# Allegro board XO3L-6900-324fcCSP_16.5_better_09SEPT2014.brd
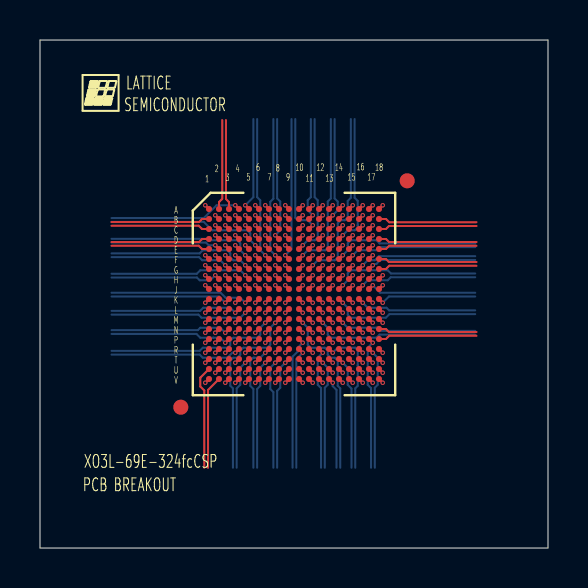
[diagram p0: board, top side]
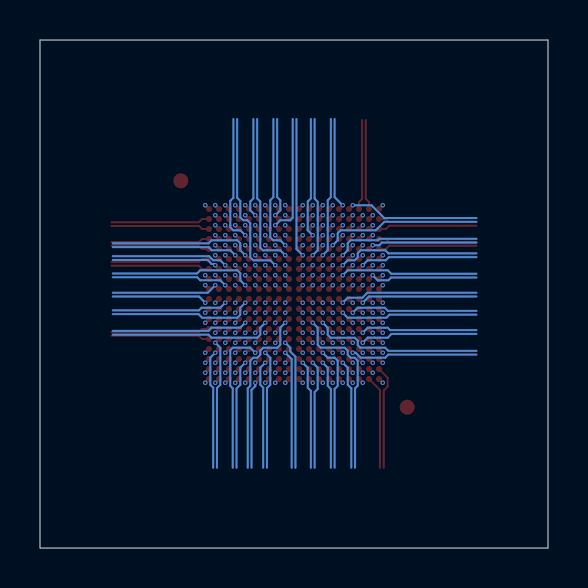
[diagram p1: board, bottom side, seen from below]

Outline 25.4 x 25.4 mm; copper layers: TOP, L2_GND, L3_SIGNAL1, L4_SIGNAL2, L5_GND, L6_SIG3, L5_PWR, BOTTOM. Coordinates in mm from the lower left corner of the outline.
Outline path: 0,25.4 25.4,25.4 25.4,0 0,0 0,25.4

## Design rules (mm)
net group CDPB4: nets PB4C PB4D
net group CDPB6: nets PB6C PB6D
net group CDPB7: nets PB7C PB7D
net group CDPB9: nets PB9C PB9D
net group CDPB13: nets PB13C PB13D
net group CDPB15: nets PB15C PB15D
net group CDPB16: nets PB16C PB16D
net group CDPB18: nets PB18C PB18D
net group CDPB21: nets PB21C PB21D
net group CDPB23: nets PB23C PB23D
net group CDPB26: nets PB26C PB26D
net group CDPB31: nets PB31C PB31D
net group CDPB35: nets PB35C PB35D
net group CDPB37: nets PB37C PB37D
net group CDPB38: nets PB38C PB38D
net group CDPL2: nets PL2C PL2D
net group CDPL3: nets PL3C PL3D
net group CDPL4: nets PL4C PL4D
net group CDPL5: nets PL5C PL5D
net group CDPL6: nets PL6C PL6D
net group CDPL7: nets PL7C PL7D
net group CDPL9: nets PL9C PL9D
net group CDPL10: nets PL10C PL10D
net group CDPL15: nets PL15C PL15D
net group CDPL16: nets PL16C PL16D
net group CDPL18: nets PL18C PL18D
net group CDPL19: nets PL19C PL19D
net group CDPL21: nets PL21C PL21D
net group CDPL23: nets PL23C PL23D
net group CDPL24: nets PL24C PL24D
net group CDPL25: nets PL25C PL25D
net group CDPR2: nets PR2C PR2D
net group CDPR3: nets PR3C PR3D
net group CDPR4: nets PR4C PR4D
net group CDPR6: nets PR6C PR6D
net group CDPR7: nets PR7C PR7D
net group CDPR8: nets PR8C PR8D
net group CDPR10: nets PR10C PR10D
net group CDPR11: nets PR11C PR11D
net group CDPR16: nets PR16C PR16D
net group CDPR17: nets PR17C PR17D
net group CDPR19: nets PR19C PR19D
net group CDPR21: nets PR21C PR21D
net group CDPR22: nets PR22C PR22D
net group CDPR23: nets PR23C PR23D
net group CDPR24: nets PR24C PR24D
net group CDPR25: nets PR25C PR25D
net group CDPT9: nets PT9C PT9D
net group CDPT10: nets PT10C PT10D
net group CDPT11: nets PT11C PT11D
net group CDPT14: nets PT14C PT14D
net group CDPT17: nets PT17C PT17D
net group CDPT18: nets PT18C PT18D
net group CDPT21: nets PT21C PT21D
net group CDPT22: nets PT22C PT22D
net group CDPT25: nets PT25C PT25D
net group CDPT26: nets PT26C PT26D
net group CDPT27: nets PT27C PT27D
net group CDPT33: nets PT33C PT33D
net group CDPT34: nets PT34C PT34D
net group CDPT35: nets PT35C PT35D
net group CDPT36: nets PT36C PT36D
net group DP1: nets PB16A PB16B
net group DP2: nets PB7A PB7B
net group DP3: nets PB13A PB13B
net group DP4: nets PB18A PB18B
net group PB4: nets PB4A PB4B
net group PB6: nets PB6A PB6B
net group PB9: nets PB9A PB9B
net group PB10: nets PB10A PB10B
net group PB12: nets PB12A PB12B
net group PB15: nets PB15A PB15B
net group PB21: nets PB21A PB21B
net group PB23: nets PB23A PB23B
net group PB26: nets PB26A PB26B
net group PB28: nets PB28A PB28B
net group PB29: nets PB29A PB29B
net group PB31: nets PB31A PB31B
net group PB32: nets PB32A PB32B
net group PB34: nets PB34A PB34B
net group PB35: nets PB35A PB35B
net group PB37: nets PB37A PB37B
net group PB38: nets PB38A PB38B
net group PL2: nets PL2A PL2B
net group PL3: nets PL3A PL3B
net group PL4: nets PL4A PL4B
net group PL5: nets PL5A PL5B
net group PL6: nets PL6A PL6B
net group PL8: nets PL8A PL8B
net group PL9: nets PL9A PL9B
net group PL10: nets PL10A PL10B
net group PL11: nets PL11A PL11B
net group PL12: nets PL12A PL12B
net group PL15: nets PL15A PL15B
net group PL17: nets PL17A PL17B
net group PL18: nets PL18A PL18B
net group PL19: nets PL19A PL19B
net group PL22: nets PL22A PL22B
net group PL23: nets PL23A PL23B
net group PL24: nets PL24A PL24B
net group PL25: nets PL25A PL25B
net group PR2: nets PR2A PR2B
net group PR3: nets PR3A PR3B
net group PR4: nets PR4A PR4B
net group PR5: nets PR5A PR5B
net group PR7: nets PR7A PR7B
net group PR8: nets PR8A PR8B
net group PR9: nets PR9A PR9B
net group PR11: nets PR11A PR11B
net group PR12: nets PR12A PR12B
net group PR15: nets PR15A PR15B
net group PR16: nets PR16A PR16B
net group PR17: nets PR17A PR17B
net group PR18: nets PR18A PR18B
net group PR21: nets PR21A PR21B
net group PR22: nets PR22A PR22B
net group PR23: nets PR23A PR23B
net group PR24: nets PR24A PR24B
net group PR25: nets PR25A PR25B
net group PT9: nets PT9A PT9B
net group PT10: nets PT10A PT10B
net group PT11: nets PT11A PT11B
net group PT12: nets PT12A PT12B
net group PT13: nets PT13A PT13B
net group PT14: nets PT14A PT14B
net group PT15: nets PT15A PT15B
net group PT16: nets PT16A PT16B
net group PT17: nets PT17A PT17B
net group PT18: nets PT18A PT18B
net group PT21: nets PT21A PT21B
net group PT22: nets PT22A PT22B
net group PT25: nets PT25A PT25B
net group PT26: nets PT26A PT26B
net group PT27: nets PT27A PT27B
net group PT28: nets PT28A PT28B
net group PT32: nets PT32A PT32B
net group PT33: nets PT33A PT33B
net group PT34: nets PT34A PT34B
net group PT35: nets PT35A PT35B
net group PT36: nets PT36A PT36B

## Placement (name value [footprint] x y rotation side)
BGA  -  [BGA324N50P18X18_1000X1000X10-1]  12.7 12.7 270 top
NOREF  -  []  1.85 21.54 0 top

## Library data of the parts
BGA = BGA324N50P18X18_1000X1000X10-1

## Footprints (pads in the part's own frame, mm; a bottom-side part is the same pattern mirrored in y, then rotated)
BGA324N50P18X18_1000X1000X10-1
  round 0.75 smd: (-5.66,5.66) (5.66,-5.66)
  round 0.305 smd: A1(-4.25,-4.25) A2(-4.25,-3.75) A3(-4.25,-3.25) A4(-4.25,-2.75) A5(-4.25,-2.25) A6(-4.25,-1.75) A7(-4.25,-1.25) A8(-4.25,-0.75) A9(-4.25,-0.25) A10(-4.25,0.25) A11(-4.25,0.75) A12(-4.25,1.25) A13(-4.25,1.75) A14(-4.25,2.25) A15(-4.25,2.75) A16(-4.25,3.25) A17(-4.25,3.75) A18(-4.25,4.25) B1(-3.75,-4.25) B2(-3.75,-3.75) B3(-3.75,-3.25) B4(-3.75,-2.75) B5(-3.75,-2.25) B6(-3.75,-1.75) B7(-3.75,-1.25) B8(-3.75,-0.75) B9(-3.75,-0.25) B10(-3.75,0.25) B11(-3.75,0.75) B12(-3.75,1.25) B13(-3.75,1.75) B14(-3.75,2.25) B15(-3.75,2.75) B16(-3.75,3.25) B17(-3.75,3.75) B18(-3.75,4.25) C1(-3.25,-4.25) C2(-3.25,-3.75) C3(-3.25,-3.25) C4(-3.25,-2.75) C5(-3.25,-2.25) C6(-3.25,-1.75) C7(-3.25,-1.25) C8(-3.25,-0.75) C9(-3.25,-0.25) C10(-3.25,0.25) C11(-3.25,0.75) C12(-3.25,1.25) C13(-3.25,1.75) C14(-3.25,2.25) C15(-3.25,2.75) C16(-3.25,3.25) C17(-3.25,3.75) C18(-3.25,4.25) D1(-2.75,-4.25) D2(-2.75,-3.75) D3(-2.75,-3.25) D4(-2.75,-2.75) D5(-2.75,-2.25) D6(-2.75,-1.75) D7(-2.75,-1.25) D8(-2.75,-0.75) D9(-2.75,-0.25) D10(-2.75,0.25) D11(-2.75,0.75) D12(-2.75,1.25) D13(-2.75,1.75) D14(-2.75,2.25) D15(-2.75,2.75) D16(-2.75,3.25) D17(-2.75,3.75) D18(-2.75,4.25) E1(-2.25,-4.25) E2(-2.25,-3.75) E3(-2.25,-3.25) E4(-2.25,-2.75) E5(-2.25,-2.25) E6(-2.25,-1.75) E7(-2.25,-1.25) E8(-2.25,-0.75) E9(-2.25,-0.25) E10(-2.25,0.25) E11(-2.25,0.75) E12(-2.25,1.25) E13(-2.25,1.75) E14(-2.25,2.25) E15(-2.25,2.75) E16(-2.25,3.25) E17(-2.25,3.75) E18(-2.25,4.25) F1(-1.75,-4.25) F2(-1.75,-3.75) F3(-1.75,-3.25) F4(-1.75,-2.75) F5(-1.75,-2.25) F6(-1.75,-1.75) F7(-1.75,-1.25) F8(-1.75,-0.75) F9(-1.75,-0.25) F10(-1.75,0.25) F11(-1.75,0.75) F12(-1.75,1.25) F13(-1.75,1.75) F14(-1.75,2.25) F15(-1.75,2.75) F16(-1.75,3.25) F17(-1.75,3.75) F18(-1.75,4.25) G1(-1.25,-4.25) G2(-1.25,-3.75) G3(-1.25,-3.25) G4(-1.25,-2.75) G5(-1.25,-2.25) G6(-1.25,-1.75) G7(-1.25,-1.25) G8(-1.25,-0.75) G9(-1.25,-0.25) G10(-1.25,0.25) G11(-1.25,0.75) G12(-1.25,1.25) G13(-1.25,1.75) G14(-1.25,2.25) G15(-1.25,2.75) G16(-1.25,3.25) G17(-1.25,3.75) G18(-1.25,4.25) H1(-0.75,-4.25) H2(-0.75,-3.75) H3(-0.75,-3.25) H4(-0.75,-2.75) H5(-0.75,-2.25) H6(-0.75,-1.75) H7(-0.75,-1.25) H8(-0.75,-0.75) H9(-0.75,-0.25) H10(-0.75,0.25) H11(-0.75,0.75) H12(-0.75,1.25) H13(-0.75,1.75) H14(-0.75,2.25) H15(-0.75,2.75) H16(-0.75,3.25) H17(-0.75,3.75) H18(-0.75,4.25) J1(-0.25,-4.25) J2(-0.25,-3.75) J3(-0.25,-3.25) J4(-0.25,-2.75) J5(-0.25,-2.25) J6(-0.25,-1.75) J7(-0.25,-1.25) J8(-0.25,-0.75) J9(-0.25,-0.25) J10(-0.25,0.25) J11(-0.25,0.75) J12(-0.25,1.25) J13(-0.25,1.75) J14(-0.25,2.25) J15(-0.25,2.75) J16(-0.25,3.25) J17(-0.25,3.75) J18(-0.25,4.25) K1(0.25,-4.25) K2(0.25,-3.75) K3(0.25,-3.25) K4(0.25,-2.75) K5(0.25,-2.25) K6(0.25,-1.75) K7(0.25,-1.25) K8(0.25,-0.75) K9(0.25,-0.25) K10(0.25,0.25) K11(0.25,0.75) K12(0.25,1.25) K13(0.25,1.75) K14(0.25,2.25) K15(0.25,2.75) K16(0.25,3.25) K17(0.25,3.75) K18(0.25,4.25) L1(0.75,-4.25) L2(0.75,-3.75) L3(0.75,-3.25) L4(0.75,-2.75) L5(0.75,-2.25) L6(0.75,-1.75) L7(0.75,-1.25) L8(0.75,-0.75) L9(0.75,-0.25) L10(0.75,0.25) L11(0.75,0.75) L12(0.75,1.25) L13(0.75,1.75) L14(0.75,2.25) L15(0.75,2.75) L16(0.75,3.25) L17(0.75,3.75) L18(0.75,4.25) M1(1.25,-4.25) M2(1.25,-3.75) M3(1.25,-3.25) M4(1.25,-2.75) M5(1.25,-2.25) M6(1.25,-1.75) M7(1.25,-1.25) M8(1.25,-0.75) M9(1.25,-0.25) M10(1.25,0.25) M11(1.25,0.75) M12(1.25,1.25) M13(1.25,1.75) M14(1.25,2.25) M15(1.25,2.75) M16(1.25,3.25) M17(1.25,3.75) M18(1.25,4.25) N1(1.75,-4.25) N2(1.75,-3.75) N3(1.75,-3.25) N4(1.75,-2.75) N5(1.75,-2.25) N6(1.75,-1.75) N7(1.75,-1.25) N8(1.75,-0.75) N9(1.75,-0.25) N10(1.75,0.25) N11(1.75,0.75) N12(1.75,1.25) N13(1.75,1.75) N14(1.75,2.25) N15(1.75,2.75) N16(1.75,3.25) N17(1.75,3.75) N18(1.75,4.25) P1(2.25,-4.25) P2(2.25,-3.75) P3(2.25,-3.25) P4(2.25,-2.75) P5(2.25,-2.25) P6(2.25,-1.75) P7(2.25,-1.25) P8(2.25,-0.75) P9(2.25,-0.25) P10(2.25,0.25) P11(2.25,0.75) P12(2.25,1.25) P13(2.25,1.75) P14(2.25,2.25) P15(2.25,2.75) P16(2.25,3.25) P17(2.25,3.75) P18(2.25,4.25) R1(2.75,-4.25) R2(2.75,-3.75) R3(2.75,-3.25) R4(2.75,-2.75) R5(2.75,-2.25) R6(2.75,-1.75) R7(2.75,-1.25) R8(2.75,-0.75) R9(2.75,-0.25) R10(2.75,0.25) R11(2.75,0.75) R12(2.75,1.25) R13(2.75,1.75) R14(2.75,2.25) R15(2.75,2.75) R16(2.75,3.25) R17(2.75,3.75) R18(2.75,4.25) T1(3.25,-4.25) T2(3.25,-3.75) T3(3.25,-3.25) T4(3.25,-2.75) T5(3.25,-2.25) T6(3.25,-1.75) T7(3.25,-1.25) T8(3.25,-0.75) T9(3.25,-0.25) T10(3.25,0.25) T11(3.25,0.75) T12(3.25,1.25) T13(3.25,1.75) T14(3.25,2.25) T15(3.25,2.75) T16(3.25,3.25) T17(3.25,3.75) T18(3.25,4.25) U1(3.75,-4.25) U2(3.75,-3.75) U3(3.75,-3.25) U4(3.75,-2.75) U5(3.75,-2.25) U6(3.75,-1.75) U7(3.75,-1.25) U8(3.75,-0.75) U9(3.75,-0.25) U10(3.75,0.25) U11(3.75,0.75) U12(3.75,1.25) U13(3.75,1.75) U14(3.75,2.25) U15(3.75,2.75) U16(3.75,3.25) U17(3.75,3.75) U18(3.75,4.25) V1(4.25,-4.25) V2(4.25,-3.75) V3(4.25,-3.25) V4(4.25,-2.75) V5(4.25,-2.25) V6(4.25,-1.75) V7(4.25,-1.25) V8(4.25,-0.75) V9(4.25,-0.25) V10(4.25,0.25) V11(4.25,0.75) V12(4.25,1.25) V13(4.25,1.75) V14(4.25,2.25) V15(4.25,2.75) V16(4.25,3.25) V17(4.25,3.75) V18(4.25,4.25)

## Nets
GND: BGA.A1 BGA.A18 BGA.F6 BGA.F13 BGA.J8 BGA.J9 BGA.J10 BGA.J11 BGA.K8 BGA.K9 BGA.K10 BGA.K11 BGA.N6 BGA.N13 BGA.V1 BGA.V18
VCC: BGA.H7 BGA.H12 BGA.J7 BGA.J12 BGA.K7 BGA.K12 BGA.L7 BGA.L12
VCCIO0: BGA.H8 BGA.H9 BGA.H10 BGA.H11
VCCIO1: BGA.H6 BGA.J6 BGA.K6 BGA.L6
VCCIO2: BGA.L8 BGA.L9 BGA.L10 BGA.L11
VCCIO3: BGA.L13 BGA.M13
VCCIO4: BGA.J13 BGA.K13
VCCIO5: BGA.G13 BGA.H13
PB4A: BGA.R15
PB4B: BGA.M11
PB4C: BGA.N11
PB4D: BGA.T15
PB6A: BGA.V17
PB6B: BGA.R14
PB6C: BGA.V16
PB6D: BGA.U16
PB7A: BGA.V14
PB7B: BGA.U14
PB7C: BGA.V15
PB7D: BGA.U15
PB9A: BGA.N10
PB9B: BGA.T13
PB9C: BGA.T14
PB9D: BGA.R13
PB10A: BGA.V13
PB10B: BGA.M10
PB12A: BGA.P13
PB12B: BGA.P12
PB13A: BGA.U13
PB13B: BGA.U12
PB13C: BGA.R12
PB13D: BGA.T12
PB15A: BGA.P11
PB15B: BGA.T11
PB15C: BGA.N9
PB15D: BGA.V12
PB16A: BGA.R11
PB16B: BGA.V11
PB16C: BGA.U11
PB16D: BGA.M9
PB18A: BGA.P10
PB18B: BGA.R10
PB18C: BGA.U10
PB18D: BGA.T10
PB21A: BGA.V10
PB21B: BGA.P9
PB21C: BGA.U9
PB21D: BGA.V9
PB23A: BGA.T9
PB23B: BGA.T8
PB23C: BGA.R9
PB23D: BGA.V8
PB26A: BGA.U8
PB26B: BGA.V7
PB26C: BGA.R8
PB26D: BGA.P8
PB28A: BGA.R7
PB28B: BGA.T7
PB29A: BGA.N8
PB29B: BGA.U7
PB31A: BGA.U6
PB31B: BGA.V6
PB31C: BGA.R6
PB31D: BGA.P6
PB32A: BGA.P7
PB32B: BGA.T6
PB34A: BGA.T5
PB34B: BGA.M8
PB35A: BGA.U5
PB35B: BGA.U4
PB35C: BGA.V5
PB35D: BGA.N7
PB37A: BGA.V4
PB37B: BGA.R5
PB37C: BGA.U3
PB37D: BGA.V3
PB38A: BGA.U2
PB38B: BGA.T4
PB38C: BGA.V2
PB38D: BGA.U1
PL2A: BGA.D16
PL2B: BGA.E15
PL2C: BGA.C17
PL2D: BGA.D17
PL3A: BGA.B18
PL3B: BGA.C18
PL3C: BGA.G12
PL3D: BGA.E17
PL4A: BGA.D18
PL4B: BGA.E18
PL4C: BGA.F15
PL4D: BGA.F14
PL5A: BGA.E16
PL5B: BGA.F16
PL5C: BGA.F17
PL5D: BGA.G14
PL6A: BGA.F18
PL6B: BGA.G18
PL6C: BGA.G15
PL6D: BGA.H14
PL7C: BGA.H17
PL7D: BGA.H15
PL8A: BGA.G16
PL8B: BGA.G17
PL9A: BGA.H16
PL9B: BGA.F12
PL9C: BGA.H18
PL9D: BGA.J15
PL10A: BGA.J14
PL10B: BGA.J16
PL10C: BGA.E14
PL10D: BGA.J18
PL11A: BGA.J17
PL11B: BGA.K18
PL12A: BGA.K17
PL12B: BGA.K15
PL15A: BGA.K16
PL15B: BGA.K14
PL15C: BGA.L17
PL15D: BGA.L14
PL16C: BGA.N12
PL16D: BGA.L15
PL17A: BGA.L18
PL17B: BGA.L16
PL18A: BGA.M16
PL18B: BGA.M18
PL18C: BGA.N14
PL18D: BGA.M17
PL19A: BGA.M15
PL19B: BGA.N17
PL19C: BGA.N16
PL19D: BGA.N15
PL21C: BGA.M14
PL21D: BGA.M12
PL22A: BGA.N18
PL22B: BGA.P18
PL23A: BGA.P15
PL23B: BGA.P16
PL23C: BGA.P17
PL23D: BGA.R17
PL24A: BGA.R16
PL24B: BGA.R18
PL24C: BGA.T17
PL24D: BGA.P14
PL25A: BGA.T18
PL25B: BGA.U17
PL25C: BGA.U18
PL25D: BGA.T16
PR2A: BGA.B1
PR2B: BGA.C1
PR2C: BGA.C3
PR2D: BGA.C2
PR3A: BGA.D1
PR3B: BGA.E1
PR3C: BGA.G7
PR3D: BGA.D3
PR4A: BGA.D2
PR4B: BGA.E4
PR4C: BGA.E3
PR4D: BGA.F3
PR5A: BGA.E2
PR5B: BGA.F5
PR6C: BGA.F4
PR6D: BGA.F2
PR7A: BGA.G6
PR7B: BGA.F1
PR7C: BGA.G5
PR7D: BGA.G3
PR8A: BGA.G4
PR8B: BGA.G2
PR8C: BGA.G1
PR8D: BGA.H4
PR9A: BGA.H5
PR9B: BGA.H2
PR10C: BGA.H3
PR10D: BGA.H1
PR11A: BGA.E5
PR11B: BGA.J5
PR11C: BGA.J4
PR11D: BGA.J1
PR12A: BGA.J3
PR12B: BGA.J2
PR15A: BGA.K1
PR15B: BGA.K2
PR16A: BGA.K3
PR16B: BGA.K5
PR16C: BGA.K4
PR16D: BGA.L3
PR17A: BGA.L1
PR17B: BGA.L2
PR17C: BGA.L5
PR17D: BGA.L4
PR18A: BGA.M1
PR18B: BGA.M6
PR19C: BGA.M3
PR19D: BGA.M4
PR21A: BGA.M2
PR21B: BGA.N1
PR21C: BGA.N2
PR21D: BGA.N4
PR22A: BGA.M5
PR22B: BGA.N5
PR22C: BGA.N3
PR22D: BGA.P3
PR23A: BGA.P2
PR23B: BGA.P1
PR23C: BGA.R1
PR23D: BGA.P4
PR24A: BGA.R2
PR24B: BGA.R3
PR24C: BGA.R4
PR24D: BGA.M7
PR25A: BGA.T1
PR25B: BGA.T2
PR25C: BGA.P5
PR25D: BGA.T3
PT9A: BGA.B16
PT9B: BGA.B17
PT9C: BGA.A17
PT9D: BGA.B15
PT10A: BGA.C16
PT10B: BGA.A15
PT10C: BGA.C14
PT10D: BGA.A16
PT11A: BGA.F11
PT11B: BGA.C15
PT11C: BGA.E13
PT11D: BGA.B14
PT12A: BGA.D13
PT12B: BGA.A14
PT12C: BGA.D15
PT13A: BGA.G11
PT13B: BGA.D14
PT14A: BGA.A13
PT14B: BGA.D12
PT14C: BGA.B13
PT14D: BGA.F10
PT15A: BGA.C13
PT15B: BGA.C12
PT16A: BGA.E12
PT16B: BGA.A12
PT16C: BGA.E11
PT17A: BGA.F9
PT17B: BGA.C11
PT17C: BGA.G10
PT17D: BGA.B12
PT18A: BGA.E10
PT18B: BGA.B11
PT18C: BGA.D11
PT18D: BGA.G9
PT21A: BGA.B10
PT21B: BGA.C10
PT21C: BGA.A11
PT21D: BGA.D10
PT22A: BGA.A10
PT22B: BGA.D9
PT22C: BGA.A9
PT22D: BGA.B9
PT25A: BGA.C9
PT25B: BGA.E9
PT25C: BGA.B8
PT25D: BGA.A8
PT26A: BGA.D8
PT26B: BGA.F8
PT26C: BGA.C8
PT26D: BGA.E8
PT27A: BGA.C7
PT27B: BGA.B3
PT27C: BGA.A7
PT27D: BGA.B7
PT28A: BGA.A6
PT28B: BGA.E7
PT32A: BGA.D7
PT32B: BGA.D6
PT33A: BGA.G8
PT33B: BGA.C6
PT33C: BGA.B5
PT33D: BGA.B6
PT34A: BGA.A4
PT34B: BGA.E6
PT34C: BGA.F7
PT34D: BGA.A5
PT35A: BGA.D4
PT35B: BGA.C5
PT35C: BGA.D5
PT35D: BGA.B2
PT36A: BGA.A3
PT36B: BGA.A2
PT36C: BGA.C4
PT36D: BGA.B4

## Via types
v1: diameter 0.224, hole 0.127, TOP to BOTTOM, 308 vias

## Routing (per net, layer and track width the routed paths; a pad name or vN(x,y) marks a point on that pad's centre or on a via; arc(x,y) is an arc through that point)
GND: length 4.2
  TOP w0.102: BGA.J8 v1(11.76,13.14) ; BGA.V18 v1(17.14,8.26) ; BGA.A18 v1(17.14,17.14) ; BGA.K10 v1(13.14,12.26) ; BGA.K9 v1(12.26,12.26) ; BGA.K11 v1(13.64,12.26) ; BGA.V1 v1(8.26,8.26) ; BGA.J11 v1(13.64,13.14) ; BGA.A1 v1(8.26,17.14) ; BGA.J10 v1(13.14,13.14) ; BGA.J9 v1(12.26,13.14) ; BGA.N6 v1(10.76,10.76) ; BGA.F6 v1(10.76,14.64) ; BGA.F13 v1(14.64,14.64) ; BGA.N13 v1(14.64,10.76) ; BGA.K8 v1(11.76,12.26)
VCC: length 2.1
  TOP w0.102: BGA.H12 v1(14.14,13.64) ; BGA.K12 v1(14.14,12.26) ; BGA.H7 v1(11.26,13.64) ; BGA.J7 v1(11.26,13.14) ; BGA.L12 v1(14.14,11.76) ; BGA.K7 v1(11.26,12.26) ; BGA.J12 v1(14.14,13.14) ; BGA.L7 v1(11.26,11.76)
VCCIO0: length 1.1
  TOP w0.102: BGA.H10 v1(13.14,13.64) ; BGA.H9 v1(12.26,13.64) ; BGA.H8 v1(11.76,13.64) ; BGA.H11 v1(13.64,13.64)
VCCIO1: length 1.1
  TOP w0.102: BGA.H6 v1(10.76,13.64) ; BGA.L6 v1(10.76,11.76) ; BGA.J6 v1(10.76,13.14) ; BGA.K6 v1(10.76,12.26)
VCCIO2: length 1.1
  TOP w0.102: BGA.L10 v1(13.14,11.76) ; BGA.L8 v1(11.76,11.76) ; BGA.L11 v1(13.64,11.76) ; BGA.L9 v1(12.26,11.76)
VCCIO3: length 0.5
  TOP w0.102: BGA.L13 v1(14.64,11.76) ; BGA.M13 v1(14.64,11.26)
VCCIO4: length 0.5
  TOP w0.102: BGA.J13 v1(14.64,13.14) ; BGA.K13 v1(14.64,12.26)
VCCIO5: length 0.5
  TOP w0.102: BGA.G13 v1(14.64,14.14) ; BGA.H13 v1(14.64,13.64)
PB4A: length 6.2
  TOP w0.102: BGA.R15 v1(15.64,9.76)
  L6_SIG3 w0.102: v1(15.64,9.76) 15.39,9.51 15.39,7.9 15.22,7.73 15.22,4.01
PB4B: length 8.5
  TOP w0.102: BGA.M11 v1(13.64,11.26)
  L6_SIG3 w0.102: 15.03,4.01 15.03,7.76 14.89,7.91 14.89,8.37 14.74,8.51 14.03,8.51 13.89,8.66 13.89,11.01 v1(13.64,11.26)
PB4C: length 10.1
  TOP w0.102: BGA.N11 v1(13.64,10.76)
  L4_SIGNAL2 w0.102: 21.82,8.87 17.44,8.87 17.29,9.01 16.03,9.01 15.89,9.16 15.89,9.87 15.74,10.01 15.57,10.01 15.53,10.01 15.39,10.16 15.39,10.37 15.24,10.51 14.53,10.51 14.39,10.66 14.39,10.86 14.24,11.01 13.89,11.01 v1(13.64,10.76)
PB4D: length 7
  TOP w0.102: BGA.T15 v1(15.64,9.26)
  L4_SIGNAL2 w0.102: v1(15.64,9.26) 15.64,9.12 15.89,8.87 15.89,8.66 16.03,8.51 17.24,8.51 17.41,8.68 21.82,8.68
PB6A: length 4.7
  TOP w0.102: BGA.V17 v1(16.64,8.26)
  L4_SIGNAL2 w0.102: 16.14,4.08 16.14,7.58 16.64,8.08 v1(16.64,8.26)
PB6B: length 6.3
  TOP w0.102: BGA.R14 v1(15.14,9.76)
  L4_SIGNAL2 w0.102: v1(15.14,9.76) 15.39,9.51 15.39,8.16 15.95,7.6 15.95,4.08
PB6C: length 4.5
  TOP w0.102: BGA.V16 v1(16.14,8.26)
  L6_SIG3 w0.102: 16.2,4.01 16.2,7.58 16.14,7.64 v1(16.14,8.26)
PB6D: length 5.1
  TOP w0.102: BGA.U16 v1(16.14,8.76)
  L6_SIG3 w0.102: v1(16.14,8.76) 16.39,8.51 16.39,8.26 16.39,8.26 16.39,4.01
PB7A: length 4.6
  TOP w0.102: BGA.V14 v1(15.14,8.26)
  L3_SIGNAL1 w0.102: 14.98,4.01 14.98,7.48 15.2,7.7 15.2,8.2 v1(15.14,8.26)
PB7B: length 5.2
  TOP w0.102: BGA.U14 v1(15.14,8.76)
  L3_SIGNAL1 w0.102: v1(15.14,8.76) 15.39,8.51 15.39,7.62 15.17,7.4 15.17,4.01
PB7C: length 4.6
  TOP w0.102: BGA.V15 v1(15.64,8.26)
  L3_SIGNAL1 w0.102: 15.48,4.01 15.48,7.25 15.57,7.34 15.57,7.35 15.7,7.48 15.7,8.2 v1(15.64,8.26)
PB7D: length 5.2
  TOP w0.102: BGA.U15 v1(15.64,8.76)
  L3_SIGNAL1 w0.102: v1(15.64,8.76) 15.89,8.51 15.89,7.39 15.67,7.17 15.67,4.01
PB9A: length 8.3
  TOP w0.102: BGA.N10 v1(13.14,10.76)
  L4_SIGNAL2 w0.102: v1(13.14,10.76) 13.39,10.51 13.76,10.51 13.89,10.39 13.89,10.16 14.03,10.01 14.74,10.01 14.89,9.87 14.89,9.2 14.89,9.2 14.89,8.07 14.73,7.92 14.73,4.11
PB9B: length 5.6
  TOP w0.102: BGA.T13 v1(14.64,9.26)
  L4_SIGNAL2 w0.102: v1(14.64,9.26) 14.39,9.01 14.39,8.08 14.54,7.92 14.54,7.67 14.54,7.67 14.54,4.11
PB9C: length 5.7
  TOP w0.102: BGA.T14 v1(15.14,9.26)
  BOTTOM w0.102: 15.57,4.01 15.57,7.97 15.39,8.16 15.39,9.01 v1(15.14,9.26)
PB9D: length 7.6
  TOP w0.102: BGA.R13 v1(14.64,9.76)
  BOTTOM w0.102: v1(14.64,9.76) 14.89,10.01 15.76,10.01 15.89,9.89 15.89,9.14 15.89,9.14 15.89,8.11 15.76,7.98 15.76,4.01
PB10A: length 4.6
  TOP w0.102: BGA.V13 v1(14.64,8.26)
  BOTTOM w0.102: v1(14.64,8.26) 14.64,8.09 14.82,7.9 14.82,4.01
PB10B: length 8.8
  TOP w0.102: BGA.M10 v1(13.14,11.26)
  BOTTOM w0.102: 15.01,4.01 15.01,7.98 14.89,8.11 14.89,9.37 14.74,9.51 14.54,9.51 14.39,9.66 14.39,9.87 14.24,10.01 13.54,10.01 13.39,10.16 13.39,11.01 v1(13.14,11.26)
PB12A: length 7.6
  TOP w0.102: BGA.P13 v1(14.64,10.26)
  L6_SIG3 w0.102: v1(14.64,10.26) 14.89,10.01 17.01,10.01 17.19,10.19 21.76,10.19
PB12B: length 8
  TOP w0.102: BGA.P12 v1(14.14,10.26)
  L6_SIG3 w0.102: v1(14.14,10.26) 14.39,10.51 17.01,10.51 17.15,10.38 21.76,10.38
PB13A: length 5.2
  TOP w0.102: BGA.U13 v1(14.64,8.76)
  L3_SIGNAL1 w0.102: v1(14.64,8.76) 14.89,8.51 14.89,8.16 14.7,7.98 14.7,4.01
PB13B: length 5.2
  TOP w0.102: BGA.U12 v1(14.14,8.76)
  L3_SIGNAL1 w0.102: 14.51,4.01 14.51,8.04 14.39,8.16 14.39,8.51 v1(14.14,8.76)
PB13C: length 6.2
  TOP w0.102: BGA.R12 v1(14.14,9.76)
  BOTTOM w0.102: v1(14.14,9.76) 13.89,9.51 13.89,8.87 13.89,8.87 13.89,8.16 14.05,8 14.05,4.01
PB13D: length 5.7
  TOP w0.102: BGA.T12 v1(14.14,9.26)
  BOTTOM w0.102: 14.24,4.01 14.24,8.01 14.39,8.16 14.39,9.01 v1(14.14,9.26)
PB15A: length 6.6
  TOP w0.102: BGA.P11 v1(13.64,10.26)
  L4_SIGNAL2 w0.102: v1(13.64,10.26) 13.39,10.01 13.39,8.11 13.54,7.95 13.54,4.08
PB15B: length 5.6
  TOP w0.102: BGA.T11 v1(13.64,9.26)
  L4_SIGNAL2 w0.102: v1(13.64,9.26) 13.89,9.01 13.89,8.11 13.73,7.95 13.73,4.08
PB15C: length 8.4
  TOP w0.102: BGA.N9 v1(12.26,10.76)
  L3_SIGNAL1 w0.102: v1(12.26,10.76) 12.51,10.51 13.74,10.51 13.89,10.36 13.89,7.67 13.91,7.65 13.91,4.01
PB15D: length 4.5
  TOP w0.102: BGA.V12 v1(14.14,8.26)
  L3_SIGNAL1 w0.102: v1(14.14,8.26) 14.14,7.66 14.1,7.62 14.1,4.01
PB16A: length 6.2
  TOP w0.102: BGA.R11 v1(13.64,9.76)
  L3_SIGNAL1 w0.102: 13.29,4.01 13.29,8.06 13.39,8.16 13.39,9.51 v1(13.64,9.76)
PB16B: length 4.6
  TOP w0.102: BGA.V11 v1(13.64,8.26)
  L3_SIGNAL1 w0.102: v1(13.64,8.26) 13.64,8.15 13.47,7.98 13.47,4.01
PB16C: length 5.2
  TOP w0.102: BGA.U11 v1(13.64,8.76)
  L6_SIG3 w0.102: v1(13.64,8.76) 13.39,8.51 13.39,8.16 13.2,7.98 13.2,4.01
PB16D: length 7.8
  TOP w0.102: BGA.M9 v1(12.26,11.26)
  L6_SIG3 w0.102: v1(12.26,11.26) 12.7,10.83 12.7,8.29 13.01,7.98 13.01,4.01
PB18A: length 6.7
  TOP w0.102: BGA.P10 v1(13.14,10.26)
  BOTTOM w0.102: 12.63,4.01 12.63,9.57 12.89,9.83 12.89,10.01 v1(13.14,10.26)
PB18B: length 6.1
  TOP w0.102: BGA.R10 v1(13.14,9.76)
  BOTTOM w0.102: 12.82,4.01 12.82,9.44 v1(13.14,9.76)
PB18C: length 5.5
  TOP w0.102: BGA.U10 v1(13.14,8.76)
  L4_SIGNAL2 w0.102: 12.78,4.08 12.78,8.82 12.88,8.92 12.98,8.92 v1(13.14,8.76)
PB18D: length 5.8
  TOP w0.102: BGA.T10 v1(13.14,9.26)
  L4_SIGNAL2 w0.102: 12.59,4.08 12.59,8.9 12.8,9.11 12.98,9.11 v1(13.14,9.26)
PB21A: length 4.6
  TOP w0.102: BGA.V10 v1(13.14,8.26)
  L3_SIGNAL1 w0.102: 12.95,4.01 12.95,8.08 v1(13.14,8.26)
PB21B: length 6.7
  TOP w0.102: BGA.P9 v1(12.26,10.26)
  L3_SIGNAL1 w0.102: 12.76,4.01 12.76,9.76 v1(12.26,10.26)
PB21C: length 5.1
  TOP w0.102: BGA.U9 v1(12.26,8.76)
  L3_SIGNAL1 w0.102: 12.51,4.01 12.51,8.51 v1(12.26,8.76)
PB21D: length 4.5
  TOP w0.102: BGA.V9 v1(12.26,8.26)
  L3_SIGNAL1 w0.102: v1(12.26,8.26) 12.26,7.98 12.32,7.92 12.32,4.01
PB23A: length 5.7
  TOP w0.102: BGA.T9 v1(12.26,9.26)
  BOTTOM w0.102: 11.86,4.01 11.86,7.86 12.01,8.01 12.01,9.01 v1(12.26,9.26)
PB23B: length 5.7
  TOP w0.102: BGA.T8 v1(11.76,9.26)
  BOTTOM w0.102: v1(11.76,9.26) 11.51,9.01 11.51,7.95 11.67,7.8 11.67,4.01
PB23C: length 6.1
  TOP w0.102: BGA.R9 v1(12.26,9.76)
  L3_SIGNAL1 w0.102: 12.01,4.01 12.01,9.51 v1(12.26,9.76)
PB23D: length 4.5
  TOP w0.102: BGA.V8 v1(11.76,8.26)
  L3_SIGNAL1 w0.102: v1(11.76,8.26) 11.76,8.01 11.83,7.95 11.83,4.01
PB26A: length 5.1
  TOP w0.102: BGA.U8 v1(11.76,8.76)
  L3_SIGNAL1 w0.102: v1(11.76,8.76) 11.51,8.51 11.51,4.01
PB26B: length 4.5
  TOP w0.102: BGA.V7 v1(11.26,8.26)
  L3_SIGNAL1 w0.102: 11.32,4.01 11.32,7.76 11.26,7.83 11.26,8.26 v1(11.26,8.26)
PB26C: length 6.2
  TOP w0.102: BGA.R8 v1(11.76,9.76)
  L4_SIGNAL2 w0.102: 11.67,4.08 11.67,7.92 11.51,8.08 11.51,9.53 11.68,9.7 11.76,9.7 11.76,9.7 v1(11.76,9.76)
PB26D: length 6.6
  TOP w0.102: BGA.P8 v1(11.76,10.26)
  L4_SIGNAL2 w0.102: 11.86,4.08 11.86,7.95 12.01,8.11 12.01,10.01 v1(11.76,10.26)
PB28A: length 6.6
  TOP w0.102: BGA.R7 v1(11.26,9.76)
  BOTTOM w0.102: v1(11.26,9.76) 11.01,9.51 11.01,9.51 10.7,9.51 10.7,9.51 10.66,9.51 10.51,9.37 10.51,8.11 10.67,7.95 10.67,4.01
PB28B: length 5.7
  TOP w0.102: BGA.T7 v1(11.26,9.26)
  BOTTOM w0.102: v1(11.26,9.26) 11.01,9.01 11.01,8.11 10.86,7.95 10.86,4.01
PB29A: length 7.2
  TOP w0.102: BGA.N8 v1(11.76,10.76)
  L6_SIG3 w0.102: 11.85,4.01 11.85,7.85 12.01,8.01 12.01,10.51 v1(11.76,10.76)
PB29B: length 5.2
  TOP w0.102: BGA.U7 v1(11.26,8.76)
  L6_SIG3 w0.102: 11.66,4.01 11.66,7.84 11.51,7.98 11.51,8.51 v1(11.26,8.76)
PB31A: length 5.1
  TOP w0.102: BGA.U6 v1(10.76,8.76)
  L3_SIGNAL1 w0.102: v1(10.76,8.76) 11.01,8.51 11.01,4.01
PB31B: length 4.5
  TOP w0.102: BGA.V6 v1(10.76,8.26)
  L3_SIGNAL1 w0.102: v1(10.76,8.26) 10.76,7.81 10.83,7.75 10.83,4.01
PB31C: length 6.2
  TOP w0.102: BGA.R6 v1(10.76,9.76)
  L6_SIG3 w0.102: 10.36,4.01 10.36,7.86 10.51,8.01 10.51,9.51 v1(10.76,9.76)
PB31D: length 7.1
  TOP w0.102: BGA.P6 v1(10.76,10.26)
  L6_SIG3 w0.102: 10.17,4.01 10.17,7.83 10.01,7.98 10.01,9.87 10.16,10.01 10.51,10.01 v1(10.76,10.26)
PB32A: length 6.6
  TOP w0.102: BGA.P7 v1(11.26,10.26)
  L4_SIGNAL2 w0.102: 10.89,4.08 10.89,7.89 11.01,8.01 11.01,10.01 v1(11.26,10.26)
PB32B: length 5.6
  TOP w0.102: BGA.T6 v1(10.76,9.26)
  L4_SIGNAL2 w0.102: v1(10.76,9.26) 10.51,9.01 10.51,8.04 10.7,7.86 10.7,4.08
PB34A: length 5.7
  TOP w0.102: BGA.T5 v1(10.26,9.26)
  BOTTOM w0.102: 9.83,4.01 9.83,7.98 10.01,8.16 10.01,9.01 v1(10.26,9.26)
PB34B: length 9.3
  TOP w0.102: BGA.M8 v1(11.76,11.26)
  BOTTOM w0.102: 9.65,4.01 9.65,7.98 9.51,8.11 9.51,9.37 9.66,9.51 9.86,9.51 10.01,9.66 10.01,9.87 10.16,10.01 11.37,10.01 11.51,10.16 11.51,11.01 v1(11.76,11.26)
PB35A: length 5.2
  TOP w0.102: BGA.U5 v1(10.26,8.76)
  L3_SIGNAL1 w0.102: v1(10.26,8.76) 10.51,8.51 10.51,7.95 10.31,7.75 10.31,4.01
PB35B: length 5.2
  TOP w0.102: BGA.U4 v1(9.76,8.76)
  L3_SIGNAL1 w0.102: 10.12,4.01 10.12,7.76 10.01,7.87 10.01,8.51 v1(9.76,8.76)
PB35C: length 4.5
  TOP w0.102: BGA.V5 v1(10.26,8.26)
  L4_SIGNAL2 w0.102: v1(10.26,8.26) 10.26,8.01 10.2,7.95 10.2,4.08
PB35D: length 7.8
  TOP w0.102: BGA.N7 v1(11.26,10.76)
  L4_SIGNAL2 w0.102: 10.01,4.08 10.01,9.36 10.16,9.51 10.33,9.51 10.33,9.51 10.37,9.51 10.51,9.66 10.51,9.7 10.51,9.7 10.51,10.37 10.66,10.51 11.01,10.51 v1(11.26,10.76)
PB37A: length 4.5
  TOP w0.102: BGA.V4 v1(9.76,8.26)
  L3_SIGNAL1 w0.102: 9.7,4.01 9.7,7.45 9.76,7.51 v1(9.76,8.26)
PB37B: length 6.5
  TOP w0.102: BGA.R5 v1(10.26,9.76)
  L3_SIGNAL1 w0.102: v1(10.26,9.76) 10.01,9.51 9.66,9.51 9.51,9.37 9.51,4.01
PB37C: length 5.2
  TOP w0.102: BGA.U3 v1(9.26,8.76)
  L3_SIGNAL1 w0.102: 8.83,4.01 8.83,7.24 9.01,7.43 9.01,8.51 v1(9.26,8.76)
PB37D: length 4.6
  TOP w0.102: BGA.V3 v1(9.26,8.26)
  L3_SIGNAL1 w0.102: 9.01,4.01 9.01,7.16 9.2,7.35 9.2,8.2 v1(9.26,8.26)
PB38A: length 5.2
  TOP w0.102: BGA.U2 v1(8.76,8.76)
  L6_SIG3 w0.102: v1(8.76,8.76) 9.01,8.51 9.01,8.01 9.17,7.86 9.17,4.01
PB38B: length 5.7
  TOP w0.102: BGA.T4 v1(9.76,9.26)
  L6_SIG3 w0.102: 9.36,4.01 9.36,7.89 9.51,8.04 9.51,9.01 v1(9.76,9.26)
PB38C: length 4.7
  TOP w0.102: BGA.V2 8.4,7.9 8.4,4.01
PB38D: length 5.2
  TOP w0.102: BGA.U1 8.01,8.51 8.01,8.08 8.21,7.88 8.21,4.01
PL2A: length 6.1
  TOP w0.102: BGA.D16 v1(16.14,15.64)
  L4_SIGNAL2 w0.102: v1(16.14,15.64) 16.28,15.64 16.53,15.89 16.89,15.89 17.04,15.73 21.82,15.73
PL2B: length 6.6
  TOP w0.102: BGA.E15 v1(15.64,15.14)
  L4_SIGNAL2 w0.102: 21.82,15.54 17.04,15.54 16.89,15.39 15.89,15.39 v1(15.64,15.14)
PL2C: length 5.5
  TOP w0.102: BGA.C17 v1(16.64,16.14)
  L3_SIGNAL1 w0.102: v1(16.64,16.14) 16.79,15.98 21.82,15.98
PL2D: length 5.5
  TOP w0.102: BGA.D17 v1(16.64,15.64)
  L3_SIGNAL1 w0.102: v1(16.64,15.64) 16.79,15.79 21.82,15.79
PL3A: length 4.9
  TOP w0.102: 21.82,16.29 17.46,16.29 17.3,16.45 BGA.B18
PL3B: length 4.9
  TOP w0.102: BGA.C18 17.3,15.95 17.45,16.1 21.82,16.1
PL3C: length 8.5
  TOP w0.102: BGA.G12 v1(14.14,14.14)
  L4_SIGNAL2 w0.102: 21.82,14.67 17.35,14.67 17.13,14.89 15.53,14.89 15.39,14.74 15.39,14.53 15.24,14.39 14.39,14.39 v1(14.14,14.14)
PL3D: length 5.6
  TOP w0.102: BGA.E17 v1(16.64,15.14)
  L4_SIGNAL2 w0.102: 21.82,14.86 17.43,14.86 17.15,15.14 v1(16.64,15.14)
PL4A: length 4.9
  TOP w0.102: BGA.D18 17.3,15.45 17.45,15.3 21.82,15.3
PL4B: length 4.9
  TOP w0.102: BGA.E18 17.3,14.95 17.46,15.11 21.82,15.11
PL4C: length 6.6
  TOP w0.102: BGA.F15 v1(15.64,14.64)
  BOTTOM w0.102: v1(15.64,14.64) 15.7,14.7 15.89,14.89 16.81,14.89 16.97,15.04 21.76,15.04
PL4D: length 7.5
  TOP w0.102: BGA.F14 v1(15.14,14.64)
  BOTTOM w0.102: v1(15.14,14.64) 15.39,14.89 15.39,15.12 15.39,15.24 15.53,15.39 16.83,15.39 16.98,15.23 21.76,15.23
PL5A: length 6.1
  TOP w0.102: BGA.E16 v1(16.14,15.14)
  L3_SIGNAL1 w0.102: v1(16.14,15.14) 16.39,15.39 16.95,15.39 17.11,15.23 21.82,15.23
PL5B: length 6.1
  TOP w0.102: BGA.F16 v1(16.14,14.64)
  L3_SIGNAL1 w0.102: 21.82,15.04 17.1,15.04 16.95,14.89 16.39,14.89 v1(16.14,14.64)
PL5C: length 5.5
  TOP w0.102: BGA.F17 v1(16.64,14.64)
  L3_SIGNAL1 w0.102: 21.82,14.57 17.07,14.57 17.01,14.64 v1(16.64,14.64)
PL5D: length 7.1
  TOP w0.102: BGA.G14 v1(15.14,14.14)
  L3_SIGNAL1 w0.102: 21.82,14.39 15.39,14.39 v1(15.14,14.14)
PL6A: length 4.9
  TOP w0.102: 21.82,14.3 17.45,14.3 17.3,14.45 BGA.F18
PL6B: length 4.9
  TOP w0.102: BGA.G18 17.3,13.95 17.46,14.11 21.82,14.11
PL6C: length 6.6
  TOP w0.102: BGA.G15 v1(15.64,14.14)
  L4_SIGNAL2 w0.102: v1(15.64,14.14) 15.89,14.39 16.83,14.39 17,14.21 21.82,14.21
PL6D: length 7.1
  TOP w0.102: BGA.H14 v1(15.14,13.64)
  L4_SIGNAL2 w0.102: v1(15.14,13.64) 15.39,13.89 16.82,13.89 16.96,14.03 21.82,14.03
PL7C: length 5.6
  TOP w0.102: BGA.H17 v1(16.64,13.64)
  L3_SIGNAL1 w0.102: v1(16.64,13.64) 16.75,13.64 17.01,13.89 21.82,13.89
PL7D: length 6.6
  TOP w0.102: BGA.H15 v1(15.64,13.64)
  L3_SIGNAL1 w0.102: v1(15.64,13.64) 15.89,13.89 16.74,13.89 16.93,14.08 21.82,14.08
PL8A: length 6.1
  TOP w0.102: BGA.G16 v1(16.14,14.14)
  BOTTOM w0.102: v1(16.14,14.14) 16.39,14.39 16.74,14.39 16.94,14.59 21.76,14.59
PL8B: length 5.5
  TOP w0.102: BGA.G17 v1(16.64,14.14)
  BOTTOM w0.102: 21.76,14.4 17.02,14.4 16.82,14.2 16.7,14.2 v1(16.64,14.14)
PL9A: length 6.1
  TOP w0.102: BGA.H16 v1(16.14,13.64)
  L4_SIGNAL2 w0.102: 21.82,13.19 17.43,13.19 17.24,13.39 16.39,13.39 v1(16.14,13.64)
PL9B: length 10.1
  TOP w0.102: BGA.F12 v1(14.14,14.64)
  L4_SIGNAL2 w0.102: v1(14.14,14.64) 13.89,14.39 13.89,13.01 14.07,12.82 17.23,12.82 17.41,13 21.82,13
PL9C: length 5.1
  TOP w0.102: BGA.H18 v1(17.14,13.64)
  L3_SIGNAL1 w0.102: v1(17.14,13.64) 17.84,13.64 18.15,13.32 21.82,13.32
PL9D: length 6.7
  TOP w0.102: BGA.J15 v1(15.64,13.14)
  L3_SIGNAL1 w0.102: v1(15.64,13.14) 15.89,13.39 17.82,13.39 18.07,13.14 21.82,13.14
PL10A: length 7.5
  TOP w0.102: BGA.J14 v1(15.14,13.14)
  BOTTOM w0.102: v1(15.14,13.14) 15.39,13.39 15.39,13.74 15.53,13.89 17.39,13.89 17.55,13.73 21.76,13.73
PL10B: length 6.1
  TOP w0.102: BGA.J16 v1(16.14,13.14)
  BOTTOM w0.102: v1(16.14,13.14) 16.39,13.39 16.39,13.39 17.39,13.39 17.54,13.54 21.76,13.54
PL10C: length 8.7
  TOP w0.102: BGA.E14 v1(15.14,15.14)
  L6_SIG3 w0.102: 21.76,14.08 18.01,14.08 17.32,13.39 15.54,13.39 15.39,13.54 15.39,14.89 v1(15.14,15.14)
PL10D: length 5.2
  TOP w0.102: BGA.J18 v1(17.14,13.14)
  L6_SIG3 w0.102: v1(17.14,13.14) 17.34,13.14 18.09,13.89 21.76,13.89
PL11A: length 5.5
  TOP w0.102: BGA.J17 v1(16.64,13.14)
  BOTTOM w0.102: 21.76,12.76 17.01,12.76 v1(16.64,13.14)
PL11B: length 5
  TOP w0.102: BGA.K18 v1(17.14,12.26)
  BOTTOM w0.102: 21.76,12.57 17.45,12.57 v1(17.14,12.26)
PL12A: length 5.7
  TOP w0.102: BGA.K17 v1(16.64,12.26)
  L3_SIGNAL1 w0.102: v1(16.64,12.26) 17,12.62 17.64,12.62 17.87,12.39 21.82,12.39
PL12B: length 6.8
  TOP w0.102: BGA.K15 v1(15.64,12.26)
  L3_SIGNAL1 w0.102: 21.82,12.58 17.95,12.58 17.7,12.82 16.2,12.82 v1(15.64,12.26)
PL15A: length 6
  TOP w0.102: BGA.K16 v1(16.14,12.26)
  BOTTOM w0.102: v1(16.14,12.26) 16.39,12.01 17.32,12.01 17.45,11.88 21.76,11.88
PL15B: length 7.5
  TOP w0.102: BGA.K14 v1(15.14,12.26)
  BOTTOM w0.102: v1(15.14,12.26) 15.39,12.01 15.39,11.66 15.54,11.51 17.29,11.51 17.47,11.69 21.76,11.69
PL15C: length 5.6
  TOP w0.102: BGA.L17 v1(16.64,11.76)
  L4_SIGNAL2 w0.102: 21.82,12.2 17.51,12.2 17.33,12.01 16.89,12.01 v1(16.64,11.76)
PL15D: length 7.6
  TOP w0.102: BGA.L14 v1(15.14,11.76)
  L4_SIGNAL2 w0.102: 21.82,12.39 17.51,12.39 17.32,12.58 15.6,12.58 15.39,12.36 15.39,12.01 v1(15.14,11.76)
PL16C: length 8
  TOP w0.102: BGA.N12 v1(14.14,10.76)
  L6_SIG3 w0.102: v1(14.14,10.76) 14.39,11.01 15.74,11.01 15.74,11.01 17.39,11.01 17.51,11.14 21.76,11.14
PL16D: length 6.6
  TOP w0.102: BGA.L15 v1(15.64,11.76)
  L6_SIG3 w0.102: 21.76,11.33 17.51,11.33 17.32,11.51 15.89,11.51 v1(15.64,11.76)
PL17A: length 5
  TOP w0.102: BGA.L18 v1(17.14,11.76)
  L3_SIGNAL1 w0.102: v1(17.14,11.76) 17.45,11.76 17.51,11.83 21.82,11.83
PL17B: length 6.1
  TOP w0.102: BGA.L16 v1(16.14,11.76)
  L3_SIGNAL1 w0.102: 21.82,12.01 16.39,12.01 v1(16.14,11.76)
PL18A: length 6.1
  TOP w0.102: BGA.M16 v1(16.14,11.26)
  L3_SIGNAL1 w0.102: 21.82,11.51 17.51,11.51 17.51,11.51 16.39,11.51 v1(16.14,11.26)
PL18B: length 5
  TOP w0.102: BGA.M18 v1(17.14,11.26)
  L3_SIGNAL1 w0.102: v1(17.14,11.26) 17.52,11.26 17.59,11.33 21.82,11.33
PL18C: length 7.1
  TOP w0.102: BGA.N14 v1(15.14,10.76)
  L4_SIGNAL2 w0.102: 21.82,11.17 17.48,11.17 17.32,11.01 17.04,11.01 15.39,11.01 v1(15.14,10.76)
PL18D: length 5.6
  TOP w0.102: BGA.M17 v1(16.64,11.26)
  L4_SIGNAL2 w0.102: v1(16.64,11.26) 16.89,11.51 17.32,11.51 17.48,11.36 21.82,11.36
PL19A: length 6.6
  TOP w0.102: BGA.M15 v1(15.64,11.26)
  L3_SIGNAL1 w0.102: 21.82,11.01 15.89,11.01 v1(15.64,11.26)
PL19B: length 5.5
  TOP w0.102: BGA.N17 v1(16.64,10.76)
  L3_SIGNAL1 w0.102: 21.82,10.83 16.95,10.83 16.89,10.76 v1(16.64,10.76)
PL19C: length 6.1
  TOP w0.102: BGA.N16 v1(16.14,10.76)
  L4_SIGNAL2 w0.102: v1(16.14,10.76) 16.39,10.51 16.82,10.51 17,10.34 18.06,10.34 18.06,10.33 21.82,10.33
PL19D: length 7
  TOP w0.102: BGA.N15 v1(15.64,10.76)
  L4_SIGNAL2 w0.102: 21.82,10.15 17.98,10.15 17.98,10.15 16.96,10.15 16.83,10.01 16.03,10.01 15.89,10.16 15.89,10.51 v1(15.64,10.76)
PL21C: length 7.1
  TOP w0.102: BGA.M14 v1(15.14,11.26)
  BOTTOM w0.102: 21.76,10.86 16.98,10.86 16.82,11.01 15.39,11.01 v1(15.14,11.26)
PL21D: length 8.5
  TOP w0.102: BGA.M12 v1(14.14,11.26)
  BOTTOM w0.102: 21.76,10.67 16.98,10.67 16.82,10.51 14.53,10.51 14.39,10.66 14.39,11.01 v1(14.14,11.26)
PL22A: length 4.9
  TOP w0.102: 21.82,10.8 17.45,10.8 17.3,10.95 BGA.N18
PL22B: length 4.9
  TOP w0.102: BGA.P18 17.3,10.45 17.46,10.61 21.82,10.61
PL23A: length 6.6
  TOP w0.102: BGA.P15 v1(15.64,10.26)
  L3_SIGNAL1 w0.102: 21.82,10.51 15.89,10.51 v1(15.64,10.26)
PL23B: length 6.2
  TOP w0.102: BGA.P16 v1(16.14,10.26)
  L3_SIGNAL1 w0.102: 21.82,10.33 17.06,10.33 16.75,10.01 16.39,10.01 v1(16.14,10.26)
PL23C: length 6.7
  TOP w0.102: BGA.P17 v1(16.64,10.26)
  BOTTOM w0.102: v1(16.64,10.26) 16.39,10.01 16.39,8.16 16.55,7.99 16.55,4.01
PL23D: length 6.2
  TOP w0.102: BGA.R17 v1(16.64,9.76)
  BOTTOM w0.102: v1(16.64,9.76) 16.89,9.51 16.89,8.16 16.74,8.01 16.74,4.01
PL24A: length 6.1
  TOP w0.102: BGA.R16 v1(16.14,9.76)
  L4_SIGNAL2 w0.102: v1(16.14,9.76) 16.39,9.51 17.64,9.51 17.82,9.33 21.82,9.33
PL24B: length 5.1
  TOP w0.102: BGA.R18 v1(17.14,9.76)
  L4_SIGNAL2 w0.102: 21.82,9.51 17.92,9.51 17.67,9.76 v1(17.14,9.76)
PL24C: length 5.6
  TOP w0.102: BGA.T17 v1(16.64,9.26)
  L3_SIGNAL1 w0.102: v1(16.64,9.26) 16.78,9.26 17.03,9.51 17.07,9.51 17.08,9.51 17.33,9.51 17.51,9.7 21.82,9.7
PL24D: length 7.9
  TOP w0.102: BGA.P14 v1(15.14,10.26)
  L3_SIGNAL1 w0.102: 21.82,9.89 17.45,9.89 17.32,10.01 17.01,10.01 16.89,9.89 16.89,9.76 16.89,9.76 16.89,9.66 16.74,9.51 15.53,9.51 15.39,9.66 15.39,10.01 v1(15.14,10.26)
PL25A: length 5
  TOP w0.102: BGA.T18 v1(17.14,9.26)
  L3_SIGNAL1 w0.102: 21.82,9.14 17.45,9.14 17.32,9.26 v1(17.14,9.26)
PL25B: length 5.6
  TOP w0.102: BGA.U17 v1(16.64,8.76)
  L3_SIGNAL1 w0.102: v1(16.64,8.76) 16.89,9.01 17.26,9.01 17.32,8.95 21.82,8.95
PL25C: length 5.2
  TOP w0.102: BGA.U18 v1(17.14,8.76)
  L3_SIGNAL1 w0.102: 17.07,4.01 17.07,7.64 17.39,7.95 17.39,8.51 v1(17.14,8.76)
PL25D: length 5.8
  TOP w0.102: BGA.T16 v1(16.14,9.26)
  L3_SIGNAL1 w0.102: 16.89,4.01 16.89,7.58 16.39,8.07 16.39,9.01 v1(16.14,9.26)
PR2A: length 4.9
  TOP w0.102: 3.58,16.3 7.95,16.3 8.1,16.45 BGA.B1
PR2B: length 4.9
  TOP w0.102: 3.58,16.11 7.94,16.11 8.1,15.95 BGA.C1
PR2C: length 6.1
  TOP w0.102: BGA.C3 v1(9.26,16.14)
  L6_SIG3 w0.102: 3.58,15.7 8.26,15.7 8.45,15.89 9.01,15.89 v1(9.26,16.14)
PR2D: length 5.6
  TOP w0.102: BGA.C2 v1(8.76,16.14)
  L6_SIG3 w0.102: v1(8.76,16.14) 8.44,16.14 8.19,15.89 3.58,15.89
PR3A: length 4.9
  TOP w0.102: BGA.D1 8.1,15.45 7.95,15.3 3.58,15.3
PR3B: length 4.9
  TOP w0.102: 3.58,15.11 7.94,15.11 8.1,14.95 BGA.E1
PR3C: length 9.9
  TOP w0.102: BGA.G7 v1(11.26,14.14)
  L4_SIGNAL2 w0.102: 3.58,16.24 5.2,16.24 5.21,16.24 8.4,16.24 8.54,16.39 9.37,16.39 9.51,16.24 9.51,16.03 9.66,15.89 10.86,15.89 11.01,15.74 11.01,14.39 v1(11.26,14.14)
PR3D: length 6.1
  TOP w0.102: BGA.D3 v1(9.26,15.64)
  L4_SIGNAL2 w0.102: 3.58,16.05 5.28,16.05 5.28,16.05 8.35,16.05 8.51,15.89 9.01,15.89 v1(9.26,15.64)
PR4A: length 5.5
  TOP w0.102: BGA.D2 v1(8.76,15.64)
  L3_SIGNAL1 w0.102: 3.58,15.82 7.95,15.82 8.14,15.64 v1(8.76,15.64)
PR4B: length 6.7
  TOP w0.102: BGA.E4 v1(9.76,15.14)
  L3_SIGNAL1 w0.102: v1(9.76,15.14) 9.62,15.14 9.37,15.39 9.33,15.39 9.33,15.39 8.66,15.39 8.6,15.45 8.06,15.45 7.87,15.64 3.58,15.64
PR4C: length 6.1
  TOP w0.102: BGA.E3 v1(9.26,15.14)
  L4_SIGNAL2 w0.102: 3.58,15.22 5.63,15.22 8.26,15.22 8.43,15.39 9.01,15.39 v1(9.26,15.14)
PR4D: length 6.1
  TOP w0.102: BGA.F3 v1(9.26,14.64)
  L4_SIGNAL2 w0.102: 3.58,15.03 5.71,15.03 8.23,15.03 8.37,14.89 9.01,14.89 v1(9.26,14.64)
PR5A: length 5.5
  TOP w0.102: BGA.E2 v1(8.76,15.14)
  BOTTOM w0.102: v1(8.76,15.14) 8.44,15.14 8.3,15.27 3.58,15.27
PR5B: length 7.5
  TOP w0.102: BGA.F5 v1(10.26,14.64)
  BOTTOM w0.102: v1(10.26,14.64) 10.01,14.89 10.01,15.24 9.87,15.39 8.51,15.39 8.44,15.46 3.58,15.46
PR6C: length 6.7
  TOP w0.102: BGA.F4 v1(9.76,14.64)
  L3_SIGNAL1 w0.102: v1(9.76,14.64) 9.51,14.89 8.66,14.89 8.35,15.2 3.58,15.2
PR6D: length 5.6
  TOP w0.102: BGA.F2 v1(8.76,14.64)
  L3_SIGNAL1 w0.102: v1(8.76,14.64) 8.64,14.64 8.26,15.01 3.58,15.01
PR7A: length 7.6
  TOP w0.102: BGA.G6 v1(10.76,14.14)
  L3_SIGNAL1 w0.102: v1(10.76,14.14) 10.51,14.39 8.16,14.39 8.1,14.45 7.94,14.45 7.94,14.45 3.58,14.45
PR7B: length 5
  TOP w0.102: BGA.F1 v1(8.26,14.64)
  L3_SIGNAL1 w0.102: v1(8.26,14.64) 8.01,14.64 8.01,14.64 3.58,14.64
PR7C: length 7.4
  TOP w0.102: BGA.G5 v1(10.26,14.14)
  BOTTOM w0.102: 3.58,14.73 7.98,14.73 8.14,14.89 8.66,14.89 8.66,14.89 9.36,14.89 9.51,14.74 9.51,14.53 9.66,14.39 10.01,14.39 v1(10.26,14.14)
PR7D: length 6.1
  TOP w0.102: BGA.G3 v1(9.26,14.14)
  BOTTOM w0.102: v1(9.26,14.14) 9.01,14.39 8.11,14.39 7.95,14.54 3.58,14.54
PR8A: length 6.6
  TOP w0.102: BGA.G4 v1(9.76,14.14)
  L4_SIGNAL2 w0.102: v1(9.76,14.14) 9.51,14.39 8.11,14.39 7.92,14.2 6.05,14.2 3.58,14.2
PR8B: length 5.6
  TOP w0.102: BGA.G2 v1(8.76,14.14)
  L4_SIGNAL2 w0.102: 3.58,14.01 6.13,14.01 7.92,14.01 8.04,13.89 8.51,13.89 v1(8.76,14.14)
PR8C: length 5
  TOP w0.102: BGA.G1 v1(8.26,14.14)
  L3_SIGNAL1 w0.102: v1(8.26,14.14) 8.08,14.14 8.01,14.07 3.58,14.07
PR8D: length 6.6
  TOP w0.102: BGA.H4 v1(9.76,13.64)
  L3_SIGNAL1 w0.102: 3.58,13.89 8.09,13.89 8.09,13.89 9.51,13.89 v1(9.76,13.64)
PR9A: length 7.1
  TOP w0.102: BGA.H5 v1(10.26,13.64)
  BOTTOM w0.102: 3.58,13.71 7.84,13.71 8.01,13.89 10.01,13.89 v1(10.26,13.64)
PR9B: length 5.6
  TOP w0.102: BGA.H2 v1(8.76,13.64)
  BOTTOM w0.102: 3.58,13.52 7.85,13.52 7.98,13.39 8.51,13.39 v1(8.76,13.64)
PR10C: length 6.1
  TOP w0.102: BGA.H3 v1(9.26,13.64)
  L3_SIGNAL1 w0.102: 3.58,13.32 7.53,13.32 7.59,13.39 9.01,13.39 v1(9.26,13.64)
PR10D: length 5
  TOP w0.102: BGA.H1 v1(8.26,13.64)
  L3_SIGNAL1 w0.102: 3.58,13.51 7.45,13.51 7.58,13.64 v1(8.26,13.64)
PR11A: length 7.3
  TOP w0.102: BGA.E5 v1(10.26,15.14)
  L6_SIG3 w0.102: v1(10.26,15.14) 10.01,14.89 8.14,14.89 7.45,14.2 3.58,14.2
PR11B: length 7.3
  TOP w0.102: BGA.J5 v1(10.26,13.14)
  L6_SIG3 w0.102: 3.58,14.01 7.54,14.01 8.16,13.39 10.01,13.39 v1(10.26,13.14)
PR11C: length 6.6
  TOP w0.102: BGA.J4 v1(9.76,13.14)
  L3_SIGNAL1 w0.102: 3.58,12.79 9.41,12.79 v1(9.76,13.14)
PR11D: length 5
  TOP w0.102: BGA.J1 v1(8.26,13.14)
  L3_SIGNAL1 w0.102: 3.58,12.98 7.7,12.98 7.86,13.14 v1(8.26,13.14)
PR12A: length 6.2
  TOP w0.102: BGA.J3 v1(9.26,13.14)
  L4_SIGNAL2 w0.102: 3.58,12.98 6.56,12.98 7.97,12.98 8.15,12.8 8.93,12.8 v1(9.26,13.14)
PR12B: length 5.6
  TOP w0.102: BGA.J2 v1(8.76,13.14)
  L4_SIGNAL2 w0.102: 3.58,13.16 6.48,13.16 7.94,13.16 8.16,13.39 8.51,13.39 v1(8.76,13.14)
PR15A: length 5.1
  TOP w0.102: BGA.K1 v1(8.26,12.26)
  L6_SIG3 w0.102: 3.58,12.54 7.99,12.54 v1(8.26,12.26)
PR15B: length 5.6
  TOP w0.102: BGA.K2 v1(8.76,12.26)
  L6_SIG3 w0.102: 3.58,12.72 8.11,12.72 8.33,12.51 8.51,12.51 v1(8.76,12.26)
PR16A: length 6.1
  TOP w0.102: BGA.K3 v1(9.26,12.26)
  BOTTOM w0.102: 3.58,12.58 8.95,12.58 v1(9.26,12.26)
PR16B: length 7.2
  TOP w0.102: BGA.K5 v1(10.26,12.26)
  BOTTOM w0.102: 3.58,12.76 9.03,12.76 9.28,12.51 10.01,12.51 v1(10.26,12.26)
PR16C: length 6.6
  TOP w0.102: BGA.K4 v1(9.76,12.26)
  L4_SIGNAL2 w0.102: v1(9.76,12.26) 9.51,12.51 8.16,12.51 7.99,12.35 6.82,12.35 3.58,12.35
PR16D: length 6.1
  TOP w0.102: BGA.L3 v1(9.26,11.76)
  L4_SIGNAL2 w0.102: 3.58,12.16 6.9,12.16 8,12.16 8.14,12.01 9.01,12.01 v1(9.26,11.76)
PR17A: length 5.1
  TOP w0.102: BGA.L1 v1(8.26,11.76)
  L3_SIGNAL1 w0.102: v1(8.26,11.76) 7.95,11.76 7.64,12.08 3.58,12.08
PR17B: length 5.7
  TOP w0.102: BGA.L2 v1(8.76,11.76)
  L3_SIGNAL1 w0.102: v1(8.76,11.76) 8.51,12.01 7.97,12.01 7.72,12.26 3.58,12.26
PR17C: length 7.1
  TOP w0.102: BGA.L5 v1(10.26,11.76)
  BOTTOM w0.102: v1(10.26,11.76) 10.01,11.51 8.08,11.51 7.92,11.67 3.58,11.67
PR17D: length 6.6
  TOP w0.102: BGA.L4 v1(9.76,11.76)
  BOTTOM w0.102: 3.58,11.86 8.01,11.86 8.16,12.01 9.51,12.01 v1(9.76,11.76)
PR18A: length 5.1
  TOP w0.102: BGA.M1 v1(8.26,11.26)
  L3_SIGNAL1 w0.102: 3.58,11.51 7.26,11.51 7.51,11.26 v1(8.26,11.26)
PR18B: length 7.6
  TOP w0.102: BGA.M6 v1(10.76,11.26)
  L3_SIGNAL1 w0.102: 3.58,11.7 7.34,11.7 7.53,11.51 10.51,11.51 v1(10.76,11.26)
PR19C: length 6.1
  TOP w0.102: BGA.M3 v1(9.26,11.26)
  L4_SIGNAL2 w0.102: 3.58,11.33 7.24,11.33 7.95,11.33 8.14,11.51 9.01,11.51 v1(9.26,11.26)
PR19D: length 6.6
  TOP w0.102: BGA.M4 v1(9.76,11.26)
  L4_SIGNAL2 w0.102: 3.58,11.14 7.32,11.14 7.95,11.14 8.08,11.01 9.51,11.01 v1(9.76,11.26)
PR21A: length 5.6
  TOP w0.102: BGA.M2 v1(8.76,11.26)
  L3_SIGNAL1 w0.102: 3.58,11.01 3.72,11.01 3.72,11.01 7.87,11.01 7.88,11.01 8.51,11.01 v1(8.76,11.26)
PR21B: length 5
  TOP w0.102: BGA.N1 v1(8.26,10.76)
  L3_SIGNAL1 w0.102: v1(8.26,10.76) 7.51,10.76 7.45,10.82 3.64,10.82 3.64,10.83 3.58,10.83
PR21C: length 5.6
  TOP w0.102: BGA.N2 v1(8.76,10.76)
  L4_SIGNAL2 w0.102: 3.58,10.36 7.64,10.36 7.64,10.36 7.86,10.36 8.02,10.51 8.37,10.51 8.62,10.76 v1(8.76,10.76)
PR21D: length 6.9
  TOP w0.102: BGA.N4 v1(9.76,10.76)
  L4_SIGNAL2 w0.102: v1(9.76,10.76) 9.51,10.51 8.66,10.51 8.51,10.37 8.51,10.16 8.37,10.01 7.98,10.01 7.83,10.17 3.58,10.17
PR22A: length 7.1
  TOP w0.102: BGA.M5 v1(10.26,11.26)
  L6_SIG3 w0.102: v1(10.26,11.26) 10.01,11.01 8.05,11.01 7.89,10.86 3.58,10.86
PR22B: length 7.1
  TOP w0.102: BGA.N5 v1(10.26,10.76)
  L6_SIG3 w0.102: v1(10.26,10.76) 10.01,10.51 8.01,10.51 7.85,10.67 3.58,10.67
PR22C: length 6.1
  TOP w0.102: BGA.N3 v1(9.26,10.76)
  BOTTOM w0.102: 3.58,10.89 7.89,10.89 8.01,11.01 9.01,11.01 v1(9.26,10.76)
PR22D: length 6.1
  TOP w0.102: BGA.P3 v1(9.26,10.26)
  BOTTOM w0.102: v1(9.26,10.26) 9.01,10.51 8.66,10.51 8.66,10.51 8.01,10.51 7.82,10.7 3.58,10.7
PR23A: length 5.6
  TOP w0.102: BGA.P2 v1(8.76,10.26)
  L3_SIGNAL1 w0.102: v1(8.76,10.26) 8.51,10.51 3.98,10.51 3.58,10.51
PR23B: length 5
  TOP w0.102: BGA.P1 v1(8.26,10.26)
  L3_SIGNAL1 w0.102: 3.58,10.33 3.98,10.33 7.45,10.33 7.51,10.26 v1(8.26,10.26)
PR23C: length 5.1
  TOP w0.102: BGA.R1 v1(8.26,9.76)
  L4_SIGNAL2 w0.102: v1(8.26,9.76) 7.89,9.76 7.45,9.33 3.58,9.33
PR23D: length 7
  TOP w0.102: BGA.P4 v1(9.76,10.26)
  L4_SIGNAL2 w0.102: v1(9.76,10.26) 9.51,10.01 9.14,10.01 9.01,9.89 9.01,9.66 8.87,9.51 7.91,9.51 7.53,9.14 3.58,9.14
PR24A: length 5.6
  TOP w0.102: BGA.R2 v1(8.76,9.76)
  L3_SIGNAL1 w0.102: v1(8.76,9.76) 8.51,10.01 8.16,10.01 8.02,9.87 3.58,9.87
PR24B: length 6.1
  TOP w0.102: BGA.R3 v1(9.26,9.76)
  L3_SIGNAL1 w0.102: v1(9.26,9.76) 9.01,9.51 8.11,9.51 7.94,9.68 3.58,9.68
PR24C: length 6.6
  TOP w0.102: BGA.R4 v1(9.76,9.76)
  BOTTOM w0.102: 3.58,9.67 7.98,9.67 8.14,9.51 9.37,9.51 9.62,9.76 v1(9.76,9.76)
PR24D: length 8.9
  TOP w0.102: BGA.M7 v1(11.26,11.26)
  BOTTOM w0.102: v1(11.26,11.26) 11.01,11.01 11.01,10.66 10.87,10.51 9.66,10.51 9.51,10.36 9.51,10.14 9.39,10.01 8.14,10.01 7.98,9.86 3.58,9.86
PR25A: length 5.1
  TOP w0.102: BGA.T1 v1(8.26,9.26)
  L3_SIGNAL1 w0.102: 3.58,9.01 7.83,9.01 8.08,9.26 v1(8.26,9.26)
PR25B: length 5.6
  TOP w0.102: BGA.T2 v1(8.76,9.26)
  L3_SIGNAL1 w0.102: v1(8.76,9.26) 8.51,9.01 8.14,9.01 7.95,8.83 3.58,8.83
PR25C: length 6.9
  TOP w0.102: BGA.P5 v1(10.26,10.26)
  L4_SIGNAL2 w0.102: 9.36,4.08 9.36,7.92 9.51,8.08 9.51,9.36 9.66,9.51 9.86,9.51 10.01,9.66 10.01,10.01 v1(10.26,10.26)
PR25D: length 5.6
  TOP w0.102: BGA.T3 v1(9.26,9.26)
  L4_SIGNAL2 w0.102: 9.17,4.08 9.17,7.95 9.01,8.11 9.01,9.01 v1(9.26,9.26)
PT9A: length 6.1
  TOP w0.102: BGA.B16 v1(16.14,16.64)
  L3_SIGNAL1 w0.102: 21.82,16.55 17.44,16.55 17.28,16.39 16.39,16.39 v1(16.14,16.64)
PT9B: length 5.5
  TOP w0.102: BGA.B17 v1(16.64,16.64)
  L3_SIGNAL1 w0.102: v1(16.64,16.64) 16.7,16.57 17.2,16.57 17.36,16.74 21.82,16.74
PT9C: length 4.6
  TOP w0.102: BGA.A17 v1(16.64,17.14)
  L3_SIGNAL1 w0.102: v1(16.64,17.14) 16.64,17.56 16.89,17.81 16.89,21.39
PT9D: length 5.7
  TOP w0.102: BGA.B15 v1(15.64,16.64)
  L3_SIGNAL1 w0.102: 16.7,21.39 16.7,17.89 16.39,17.57 16.39,17.03 16.24,16.89 15.89,16.89 v1(15.64,16.64)
PT10A: length 6.1
  TOP w0.102: BGA.C16 v1(16.14,16.14)
  L3_SIGNAL1 w0.102: v1(16.14,16.14) 15.89,16.39 15.54,16.39 15.39,16.53 15.39,17.24 15.45,17.3 15.45,21.39
PT10B: length 4.5
  TOP w0.102: BGA.A15 v1(15.64,17.14)
  L3_SIGNAL1 w0.102: 15.64,21.39 v1(15.64,17.14)
PT10C: length 6.1
  TOP w0.102: BGA.C14 v1(15.14,16.14)
  L6_SIG3 w0.102: 15.95,21.45 15.95,17.32 15.89,17.26 15.89,16.57 15.89,16.57 15.89,16.53 15.74,16.39 15.7,16.39 15.7,16.39 15.39,16.39 v1(15.14,16.14)
PT10D: length 4.6
  TOP w0.102: BGA.A16 v1(16.14,17.14)
  L6_SIG3 w0.102: 16.14,21.45 v1(16.14,17.14)
PT11A: length 9.8
  TOP w0.102: BGA.F11 v1(13.64,14.64)
  L4_SIGNAL2 w0.102: 21.82,16.54 17.04,16.54 16.89,16.39 16.53,16.39 16.39,16.24 16.39,16.04 16.24,15.89 15.54,15.89 15.39,15.74 15.39,15.04 15.24,14.89 13.89,14.89 v1(13.64,14.64)
PT11B: length 7
  TOP w0.102: BGA.C15 v1(15.64,16.14)
  L4_SIGNAL2 w0.102: v1(15.64,16.14) 15.89,16.39 15.89,16.74 16.03,16.89 16.89,16.89 17.04,16.73 21.82,16.73
PT11C: length 6.7
  TOP w0.102: BGA.E13 v1(14.64,15.14)
  L4_SIGNAL2 w0.102: v1(14.64,15.14) 14.89,15.39 14.89,17.48 15.04,17.64 15.04,21.39
PT11D: length 5.2
  TOP w0.102: BGA.B14 v1(15.14,16.64)
  L4_SIGNAL2 w0.102: 15.23,21.39 15.23,17.64 15.39,17.48 15.39,16.89 v1(15.14,16.64)
PT12A: length 6.1
  TOP w0.102: BGA.D13 v1(14.64,15.64)
  L3_SIGNAL1 w0.102: 14.95,21.39 14.95,17.45 14.89,17.39 14.89,15.89 v1(14.64,15.64)
PT12B: length 4.5
  TOP w0.102: BGA.A14 v1(15.14,17.14)
  L3_SIGNAL1 w0.102: 15.14,21.39 v1(15.14,17.14)
PT12C: length 6.5
  TOP w0.102: BGA.D15 v1(15.64,15.64)
  L6_SIG3 w0.102: v1(15.64,15.64) 15.89,15.89 21.76,15.89
PT13A: length 9
  TOP w0.102: BGA.G11 v1(13.64,14.14)
  BOTTOM w0.102: 15.54,21.45 15.54,17.51 15.39,17.35 15.39,16.53 15.24,16.39 15.04,16.39 14.89,16.24 14.89,14.54 14.74,14.39 13.89,14.39 v1(13.64,14.14)
PT13B: length 6.7
  TOP w0.102: BGA.D14 v1(15.14,15.64)
  BOTTOM w0.102: 15.73,21.45 15.73,17.51 15.89,17.36 15.89,16.82 15.89,16.82 15.89,16.14 15.89,16.03 15.74,15.89 15.39,15.89 v1(15.14,15.64)
PT14A: length 4.5
  TOP w0.102: BGA.A13 v1(14.64,17.14)
  L3_SIGNAL1 w0.102: v1(14.64,17.14) 14.64,17.39 14.57,17.45 14.57,21.39
PT14B: length 6.1
  TOP w0.102: BGA.D12 v1(14.14,15.64)
  L3_SIGNAL1 w0.102: 14.39,21.39 14.39,17.59 14.39,17.59 14.39,15.89 v1(14.14,15.64)
PT14C: length 5.2
  TOP w0.102: BGA.B13 v1(14.64,16.64)
  BOTTOM w0.102: v1(14.64,16.64) 14.89,16.89 14.89,17.32 14.73,17.48 14.73,21.45
PT14D: length 8.2
  TOP w0.102: BGA.F10 v1(13.14,14.64)
  BOTTOM w0.102: v1(13.14,14.64) 13.39,14.89 14.26,14.89 14.39,15.01 14.39,17.32 14.54,17.48 14.54,21.45
PT15A: length 5.7
  TOP w0.102: BGA.C13 v1(14.64,16.14)
  L6_SIG3 w0.102: v1(14.64,16.14) 14.89,16.39 14.89,17.24 14.74,17.39 14.74,21.45
PT15B: length 5.7
  TOP w0.102: BGA.C12 v1(14.14,16.14)
  L6_SIG3 w0.102: 14.55,21.45 14.55,17.4 14.39,17.24 14.39,16.54 14.14,16.28 v1(14.14,16.14)
PT16A: length 6.6
  TOP w0.102: BGA.E12 v1(14.14,15.14)
  L3_SIGNAL1 w0.102: 13.95,21.39 13.95,17.45 13.89,17.39 13.89,15.39 v1(14.14,15.14)
PT16B: length 4.5
  TOP w0.102: BGA.A12 v1(14.14,17.14)
  L3_SIGNAL1 w0.102: v1(14.14,17.14) 14.14,21.39
PT16C: length 6.7
  TOP w0.102: BGA.E11 v1(13.64,15.14)
  L6_SIG3 w0.102: 13.89,21.45 13.89,15.39 v1(13.64,15.14)
PT17A: length 7.2
  TOP w0.102: BGA.F9 v1(12.26,14.64)
  BOTTOM w0.102: 12.58,21.45 12.58,14.95 v1(12.26,14.64)
PT17B: length 6.2
  TOP w0.102: BGA.C11 v1(13.64,16.14)
  BOTTOM w0.102: v1(13.64,16.14) 13.39,16.39 12.89,16.39 12.76,16.51 12.76,21.45
PT17C: length 8
  TOP w0.102: BGA.G10 v1(13.14,14.14)
  L4_SIGNAL2 w0.102: 14.04,21.39 14.04,17.64 13.89,17.48 13.89,16.51 13.76,16.39 13.53,16.39 13.39,16.24 13.39,14.39 v1(13.14,14.14)
PT17D: length 5.2
  TOP w0.102: BGA.B12 v1(14.14,16.64)
  L4_SIGNAL2 w0.102: v1(14.14,16.64) 14.39,16.89 14.39,17.51 14.23,17.67 14.23,21.39
PT18A: length 7.2
  TOP w0.102: BGA.E10 v1(13.14,15.14)
  BOTTOM w0.102: 13.73,21.45 13.73,17.54 13.89,17.39 13.89,16.01 13.89,16.01 13.89,15.53 13.74,15.39 13.39,15.39 v1(13.14,15.14)
PT18B: length 5.2
  TOP w0.102: BGA.B11 v1(13.64,16.64)
  BOTTOM w0.102: v1(13.64,16.64) 13.39,16.89 13.39,17.38 13.54,17.54 13.54,21.45
PT18C: length 6.6
  TOP w0.102: BGA.D11 v1(13.64,15.64)
  L6_SIG3 w0.102: v1(13.64,15.64) 13.39,15.89 13.01,15.89 12.83,16.08 12.83,21.45
PT18D: length 7.7
  TOP w0.102: BGA.G9 v1(12.26,14.14)
  L6_SIG3 w0.102: v1(12.26,14.14) 12.64,14.51 12.64,21.45
PT21A: length 5.2
  TOP w0.102: BGA.B10 v1(13.14,16.64)
  L4_SIGNAL2 w0.102: v1(13.14,16.64) 13.39,16.89 13.39,17.45 13.2,17.64 13.2,21.39
PT21B: length 5.7
  TOP w0.102: BGA.C10 v1(13.14,16.14)
  L4_SIGNAL2 w0.102: v1(13.14,16.14) 12.8,16.47 12.8,17.42 13.01,17.64 13.01,21.39
PT21C: length 4.5
  TOP w0.102: BGA.A11 v1(13.64,17.14)
  L3_SIGNAL1 w0.102: v1(13.64,17.14) 13.64,21.39
PT21D: length 6.1
  TOP w0.102: BGA.D10 v1(13.14,15.64)
  L3_SIGNAL1 w0.102: v1(13.14,15.64) 13.39,15.89 13.39,17.32 13.45,17.39 13.45,21.39
